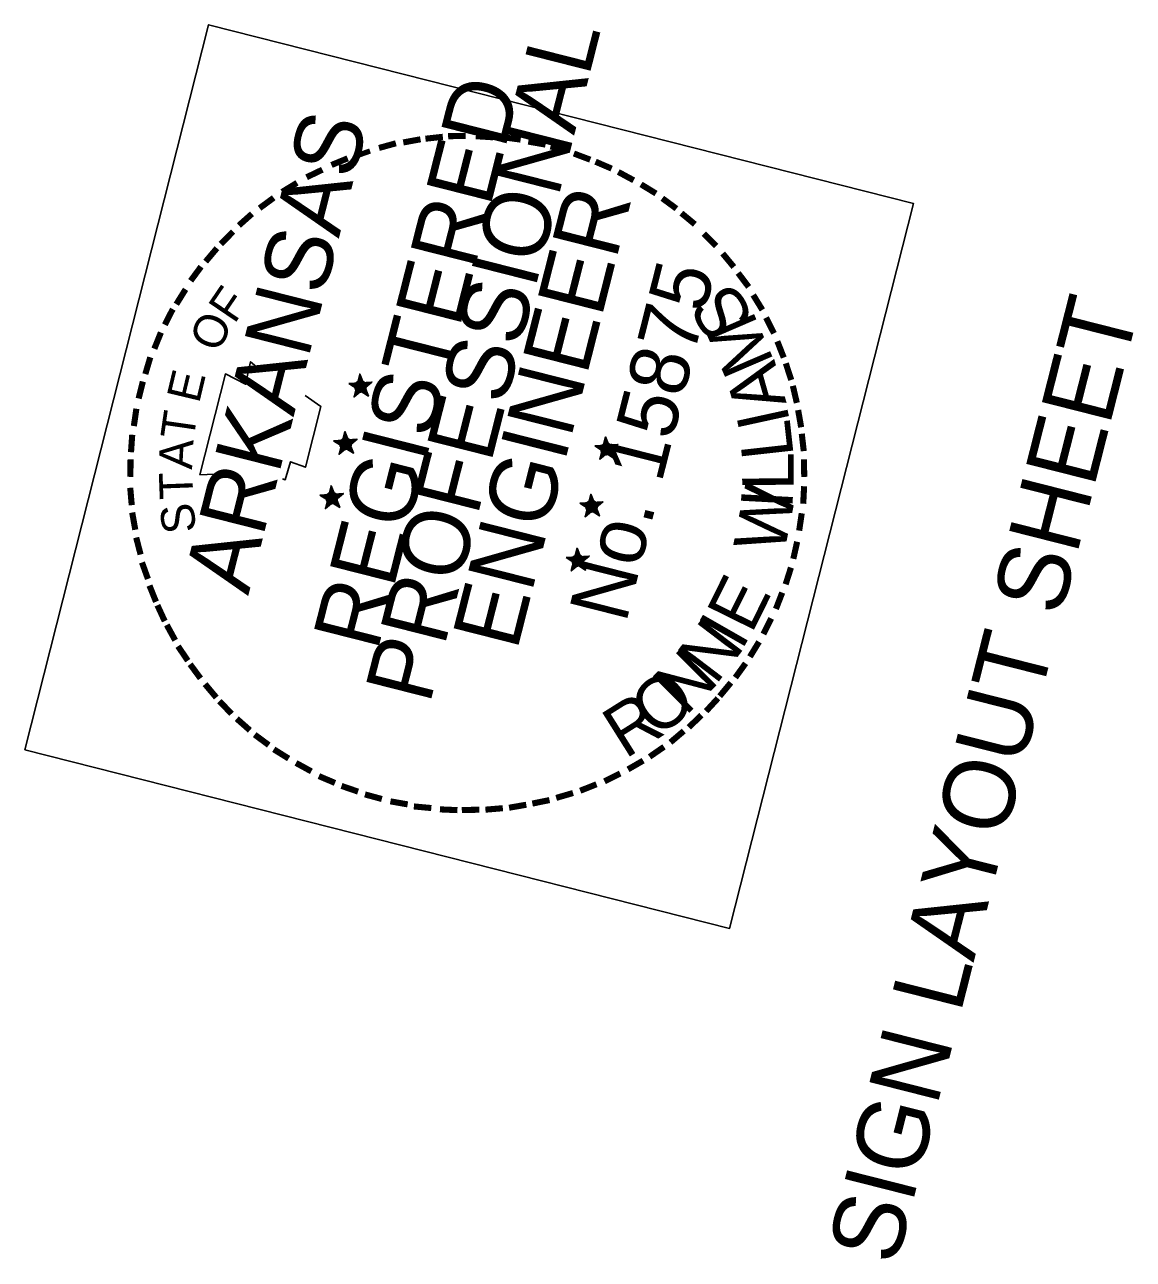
# Model space of a CAD drawing. Extents: x 670257 to 671518, y 737783 to 738188.
# Drawn here: x 670603.63 to 670611.9, y 738094.6 to 738103.81 of the extents above; entities that cross this region are included whole.
import ezdxf

# ---------------------------------------------------------------- set-up
doc = ezdxf.new("R2010")
doc.units = 0
for name, color, linetype in [('R_Border Notes', 7, 'Continuous'), ('R_Border PE', 7, 'Continuous'), ('R_Border Prem', 7, 'Continuous')]:
    doc.layers.add(name, color=color, linetype=linetype)

msp = doc.modelspace()

# ---------------------------------------------------------------- linework, layer by layer
at = {"layer": 'R_Border PE'}
for p, q in [((670606.1276, 738101.1982), (670606.1134, 738101.1219)), ((670606.1276, 738101.1982), (670606.1219, 738101.1249)), ((670606.1276, 738101.1982), (670606.1268, 738101.1237)), ((670606.1276, 738101.1982), (670606.1328, 738101.1067)), ((670606.1276, 738101.1982), (670606.1359, 738101.1394)), ((670606.1276, 738101.1982), (670606.1389, 738101.1412)), ((670606.1276, 738101.1982), (670606.1426, 738101.1454)), ((670606.0455, 738101.1288), (670606.1104, 738101.1304)), ((670606.1328, 738101.1067), (670606.0455, 738101.1288)), ((670606.0455, 738101.1288), (670606.1092, 738101.1255)), ((670606.0455, 738101.1288), (670606.1049, 738101.1189)), ((670606.0455, 738101.1288), (670606.1049, 738101.1086)), ((670606.0455, 738101.1288), (670606.1036, 738101.1037)), ((670606.0455, 738101.1288), (670606.1, 738101.0995)), ((670606.0846, 738101.0286), (670606.1328, 738101.1067)), ((670606.0846, 738101.0286), (670606.1078, 738101.0898)), ((670606.2184, 738101.1391), (670606.1328, 738101.1067)), ((670606.1919, 738101.0349), (670606.1328, 738101.1067)), ((670606.2184, 738101.1391), (670606.1401, 738101.1254)), ((670606.2184, 738101.1391), (670606.1413, 738101.1303)), ((670606.2184, 738101.1391), (670606.1492, 738101.1205)), ((670606.2184, 738101.1391), (670606.1521, 738101.1017)), ((670606.1919, 738101.0349), (670606.1521, 738101.1017)), ((670606.1919, 738101.0349), (670606.1521, 738101.0914)), ((670606.2184, 738101.1391), (670606.157, 738101.1108)), ((670606.2184, 738101.1391), (670606.1594, 738101.0999)), ((670606.1919, 738101.0349), (670606.16, 738101.1023)), ((670606.0846, 738101.0286), (670606.1121, 738101.0861)), ((670606.0846, 738101.0286), (670606.1145, 738101.0855)), ((670606.0846, 738101.0286), (670606.1236, 738101.0806)), ((670606.0846, 738101.0286), (670606.1284, 738101.0794)), ((670606.0846, 738101.0286), (670606.1333, 738101.0782)), ((670606.1919, 738101.0349), (670606.1315, 738101.0812)), ((670606.1919, 738101.0349), (670606.1393, 738101.0818)), ((670606.1919, 738101.0349), (670606.143, 738101.086)), ((670606.0164, 738100.7699), (670606.0022, 738100.6936)), ((670606.0164, 738100.7699), (670606.0107, 738100.6966)), ((670606.0164, 738100.7699), (670606.0155, 738100.6953)), ((670606.0164, 738100.7699), (670606.0216, 738100.6783)), ((670606.0164, 738100.7699), (670606.0247, 738100.7111)), ((670606.0164, 738100.7699), (670606.0283, 738100.7153)), ((670606.0164, 738100.7699), (670606.0314, 738100.7171)), ((670607.9614, 738100.7306), (670607.9478, 738100.6566)), ((670607.9614, 738100.7306), (670607.9563, 738100.6596)), ((670607.9614, 738100.7306), (670607.9612, 738100.6584)), ((670607.9614, 738100.7306), (670607.9672, 738100.6414)), ((670607.9614, 738100.7306), (670607.9697, 738100.6717)), ((670607.9614, 738100.7306), (670607.9758, 738100.6753)), ((670607.9614, 738100.7306), (670607.9788, 738100.6771)), ((670605.9319, 738100.7011), (670605.9992, 738100.7021)), ((670606.0216, 738100.6783), (670605.9319, 738100.7011)), ((670605.9319, 738100.7011), (670605.9955, 738100.6978)), ((670605.9319, 738100.7011), (670605.9937, 738100.6906)), ((670605.9319, 738100.7011), (670605.9912, 738100.6809)), ((670605.9319, 738100.7011), (670605.9924, 738100.6754)), ((670605.9319, 738100.7011), (670605.9894, 738100.6736)), ((670605.9734, 738100.6003), (670606.0216, 738100.6783)), ((670605.9734, 738100.6003), (670605.9942, 738100.6621)), ((670605.9734, 738100.6003), (670605.9991, 738100.6608)), ((670605.9734, 738100.6003), (670606.0033, 738100.6572)), ((670605.9734, 738100.6003), (670606.0124, 738100.6523)), ((670605.9734, 738100.6003), (670606.0172, 738100.6511)), ((670605.9734, 738100.6003), (670606.0221, 738100.6498)), ((670606.0813, 738100.609), (670606.0203, 738100.6529)), ((670606.1078, 738100.7132), (670606.0216, 738100.6783)), ((670606.0813, 738100.609), (670606.0216, 738100.6783)), ((670606.1078, 738100.7132), (670606.0277, 738100.7026)), ((670606.0813, 738100.609), (670606.0281, 738100.6535)), ((670606.1078, 738100.7132), (670606.0289, 738100.6971)), ((670606.0813, 738100.609), (670606.0318, 738100.6577)), ((670606.1078, 738100.7132), (670606.038, 738100.6922)), ((670606.1078, 738100.7132), (670606.0409, 738100.6734)), ((670606.0813, 738100.609), (670606.0409, 738100.6734)), ((670606.0813, 738100.609), (670606.0409, 738100.6631)), ((670606.1078, 738100.7132), (670606.0458, 738100.6825)), ((670606.1078, 738100.7132), (670606.0482, 738100.6716)), ((670606.0813, 738100.609), (670606.0488, 738100.674)), ((670607.9672, 738100.6414), (670607.8799, 738100.6635)), ((670607.8799, 738100.6635), (670607.9442, 738100.6627)), ((670607.8799, 738100.6635), (670607.9436, 738100.6603)), ((670607.8799, 738100.6635), (670607.9418, 738100.653)), ((670607.8799, 738100.6635), (670607.9393, 738100.6433)), ((670607.8799, 738100.6635), (670607.9381, 738100.6385)), ((670607.8799, 738100.6635), (670607.9368, 738100.6336)), ((670607.919, 738100.5633), (670607.9672, 738100.6414)), ((670608.0528, 738100.6739), (670607.9672, 738100.6414)), ((670608.0264, 738100.5697), (670607.9672, 738100.6414)), ((670608.0528, 738100.6739), (670607.9739, 738100.6577)), ((670608.0528, 738100.6739), (670607.9751, 738100.6626)), ((670608.0528, 738100.6739), (670607.9854, 738100.6523)), ((670608.0528, 738100.6739), (670607.9884, 738100.6334)), ((670608.0264, 738100.5697), (670607.9884, 738100.6334)), ((670608.0528, 738100.6739), (670607.9908, 738100.6431)), ((670608.0264, 738100.5697), (670607.9938, 738100.6346)), ((670608.0528, 738100.6739), (670607.9956, 738100.6316)), ((670607.919, 738100.5633), (670607.9416, 738100.6221)), ((670607.919, 738100.5633), (670607.9465, 738100.6209)), ((670607.919, 738100.5633), (670607.9507, 738100.6172)), ((670607.919, 738100.5633), (670607.958, 738100.6154)), ((670607.919, 738100.5633), (670607.9646, 738100.6111)), ((670607.919, 738100.5633), (670607.9695, 738100.6099)), ((670608.0264, 738100.5697), (670607.9653, 738100.6135)), ((670608.0264, 738100.5697), (670607.9756, 738100.6135)), ((670608.0264, 738100.5697), (670607.9798, 738100.6201)), ((670608.0264, 738100.5697), (670607.9865, 738100.6262)), ((670605.9138, 738100.3652), (670605.8996, 738100.2889)), ((670605.9138, 738100.3652), (670605.9081, 738100.2919)), ((670605.9138, 738100.3652), (670605.9129, 738100.2907)), ((670605.9138, 738100.3652), (670605.9189, 738100.2737)), ((670605.9138, 738100.3652), (670605.9221, 738100.3064)), ((670605.9138, 738100.3652), (670605.9257, 738100.3106)), ((670605.9138, 738100.3652), (670605.9287, 738100.3124)), ((670605.8293, 738100.2964), (670605.8966, 738100.2974)), ((670605.9189, 738100.2737), (670605.8293, 738100.2964)), ((670605.8293, 738100.2964), (670605.8929, 738100.2932)), ((670605.8293, 738100.2964), (670605.8917, 738100.2883)), ((670605.8293, 738100.2964), (670605.8892, 738100.2786)), ((670605.8293, 738100.2964), (670605.8898, 738100.2707)), ((670605.8293, 738100.2964), (670605.8868, 738100.2689)), ((670605.8707, 738100.1956), (670605.9189, 738100.2737)), ((670606.0051, 738100.3085), (670605.9189, 738100.2737)), ((670605.9787, 738100.2043), (670605.9189, 738100.2737)), ((670606.0051, 738100.3085), (670605.9251, 738100.2979)), ((670606.0051, 738100.3085), (670605.9263, 738100.2924)), ((670606.0051, 738100.3085), (670605.9353, 738100.2875)), ((670606.0051, 738100.3085), (670605.9383, 738100.2687)), ((670605.9787, 738100.2043), (670605.9383, 738100.2687)), ((670606.0051, 738100.3085), (670605.9432, 738100.2778)), ((670606.0051, 738100.3085), (670605.9456, 738100.2669)), ((670605.9787, 738100.2043), (670605.9462, 738100.2693)), ((670607.8502, 738100.3022), (670607.8366, 738100.2283)), ((670607.8502, 738100.3022), (670607.8451, 738100.2313)), ((670607.8502, 738100.3022), (670607.85, 738100.2301)), ((670607.8502, 738100.3022), (670607.856, 738100.2131)), ((670607.8502, 738100.3022), (670607.8585, 738100.2434)), ((670607.8502, 738100.3022), (670607.8622, 738100.2476)), ((670607.8502, 738100.3022), (670607.8682, 738100.2513)), ((670605.8707, 738100.1956), (670605.8916, 738100.2574)), ((670605.8707, 738100.1956), (670605.8964, 738100.2562)), ((670605.8707, 738100.1956), (670605.9007, 738100.2525)), ((670605.8707, 738100.1956), (670605.9103, 738100.25)), ((670605.8707, 738100.1956), (670605.9146, 738100.2464)), ((670605.8707, 738100.1956), (670605.9194, 738100.2452)), ((670605.9787, 738100.2043), (670605.9176, 738100.2482)), ((670605.9787, 738100.2043), (670605.9255, 738100.2488)), ((670605.9787, 738100.2043), (670605.9292, 738100.253)), ((670605.9787, 738100.2043), (670605.9383, 738100.2584)), ((670607.856, 738100.2131), (670607.7687, 738100.2352)), ((670607.7687, 738100.2352), (670607.833, 738100.2344)), ((670607.7687, 738100.2352), (670607.8324, 738100.232)), ((670607.7687, 738100.2352), (670607.8305, 738100.2247)), ((670607.7687, 738100.2352), (670607.8281, 738100.215)), ((670607.7687, 738100.2352), (670607.8269, 738100.2102)), ((670607.7687, 738100.2352), (670607.8232, 738100.2059)), ((670607.8078, 738100.135), (670607.856, 738100.2131)), ((670607.8078, 738100.135), (670607.8304, 738100.1938)), ((670607.8078, 738100.135), (670607.8353, 738100.1926)), ((670607.8078, 738100.135), (670607.8377, 738100.1919)), ((670607.8078, 738100.135), (670607.8468, 738100.1871)), ((670607.8078, 738100.135), (670607.8516, 738100.1858)), ((670607.8078, 738100.135), (670607.8565, 738100.1846)), ((670607.9151, 738100.1413), (670607.8547, 738100.1876)), ((670607.9416, 738100.2455), (670607.856, 738100.2131)), ((670607.9151, 738100.1413), (670607.856, 738100.2131)), ((670607.9416, 738100.2455), (670607.8627, 738100.2294)), ((670607.9416, 738100.2455), (670607.8645, 738100.2367)), ((670607.9151, 738100.1413), (670607.865, 738100.1876)), ((670607.9151, 738100.1413), (670607.8686, 738100.1918)), ((670607.9416, 738100.2455), (670607.8724, 738100.227)), ((670607.9151, 738100.1413), (670607.8753, 738100.1979)), ((670607.9151, 738100.1413), (670607.8754, 738100.2082)), ((670607.9416, 738100.2455), (670607.8778, 738100.2076)), ((670607.9416, 738100.2455), (670607.8796, 738100.2148)), ((670607.9416, 738100.2455), (670607.882, 738100.2039)), ((670607.9151, 738100.1413), (670607.8826, 738100.2063)), ((670607.7482, 738099.9), (670607.734, 738099.8236)), ((670607.7482, 738099.9), (670607.7425, 738099.8266)), ((670607.7482, 738099.9), (670607.7473, 738099.8254)), ((670607.7482, 738099.9), (670607.7533, 738099.8084)), ((670607.7482, 738099.9), (670607.7559, 738099.8387)), ((670607.7482, 738099.9), (670607.7595, 738099.8429)), ((670607.7482, 738099.9), (670607.7656, 738099.8466)), ((670607.6661, 738099.8305), (670607.731, 738099.8321)), ((670607.7533, 738099.8084), (670607.6661, 738099.8305)), ((670607.6661, 738099.8305), (670607.7298, 738099.8273)), ((670607.6661, 738099.8305), (670607.7279, 738099.82)), ((670607.6661, 738099.8305), (670607.7254, 738099.8103)), ((670607.6661, 738099.8305), (670607.7242, 738099.8055)), ((670607.6661, 738099.8305), (670607.7206, 738099.8012)), ((670607.7052, 738099.7304), (670607.7533, 738099.8084)), ((670607.8389, 738099.8409), (670607.7533, 738099.8084)), ((670607.8125, 738099.7367), (670607.7533, 738099.8084)), ((670607.8389, 738099.8409), (670607.7601, 738099.8248)), ((670607.8389, 738099.8409), (670607.7619, 738099.832)), ((670607.8389, 738099.8409), (670607.7698, 738099.8223)), ((670607.8125, 738099.7367), (670607.7727, 738099.8035)), ((670607.8389, 738099.8409), (670607.7751, 738099.8029)), ((670607.8389, 738099.8409), (670607.777, 738099.8101)), ((670607.8389, 738099.8409), (670607.7794, 738099.7992)), ((670607.8125, 738099.7367), (670607.78, 738099.8016)), ((670607.7052, 738099.7304), (670607.7284, 738099.7915)), ((670607.7052, 738099.7304), (670607.7326, 738099.7879)), ((670607.7052, 738099.7304), (670607.7351, 738099.7872)), ((670607.7052, 738099.7304), (670607.7441, 738099.7824)), ((670607.7052, 738099.7304), (670607.749, 738099.7811)), ((670607.7052, 738099.7304), (670607.7538, 738099.7799)), ((670607.8125, 738099.7367), (670607.752, 738099.7829)), ((670607.8125, 738099.7367), (670607.7623, 738099.7829)), ((670607.8125, 738099.7367), (670607.766, 738099.7871)), ((670607.8125, 738099.7367), (670607.7727, 738099.7932))]:
    msp.add_line(p, q, dxfattribs=at)
for points in [[(670605.3723, 738101.2402), (670605.313, 738101.2913), (670605.2754, 738101.1229), (670605.1247, 738101.1998), (670604.9336, 738100.4462)], [(670606.0455, 738101.1288), (670606.2184, 738101.1391), (670606.0846, 738101.0286), (670606.1276, 738101.1982), (670606.1919, 738101.0349), (670606.0455, 738101.1288)], [(670605.5501, 738100.4162), (670605.5719, 738100.4107), (670605.6112, 738100.5451), (670605.722, 738100.5041), (670605.837, 738100.9573), (670605.7208, 738101.0383)], [(670605.9319, 738100.7011), (670606.1078, 738100.7132), (670605.9734, 738100.6003), (670606.0164, 738100.7699), (670606.0813, 738100.609), (670605.9319, 738100.7011)], [(670607.8799, 738100.6635), (670608.0528, 738100.6739), (670607.919, 738100.5633), (670607.9614, 738100.7306), (670608.0264, 738100.5697), (670607.8799, 738100.6635)], [(670604.9336, 738100.4462), (670605.1507, 738100.4582)], [(670605.8293, 738100.2964), (670606.0051, 738100.3085), (670605.8707, 738100.1956), (670605.9138, 738100.3652), (670605.9787, 738100.2043), (670605.8293, 738100.2964)], [(670607.7687, 738100.2352), (670607.9416, 738100.2455), (670607.8078, 738100.135), (670607.8502, 738100.3022), (670607.9151, 738100.1413), (670607.7687, 738100.2352)], [(670607.6661, 738099.8305), (670607.8389, 738099.8409), (670607.7052, 738099.7304), (670607.7482, 738099.9), (670607.8125, 738099.7367), (670607.6661, 738099.8305)]]:
    msp.add_lwpolyline(points, dxfattribs=at)
for centre, radius in [((670606.1333, 738101.1063), 0.0431), ((670606.1333, 738101.1063), 0.039), ((670606.1333, 738101.1063), 0.0361), ((670606.1333, 738101.1063), 0.0332), ((670606.1333, 738101.1063), 0.0289), ((670606.1333, 738101.1063), 0.0269), ((670606.1333, 738101.1063), 0.0248), ((670606.1333, 738101.1063), 0.0213), ((670606.1333, 738101.1063), 0.0187), ((670606.1333, 738101.1063), 0.0155), ((670606.1333, 738101.1063), 0.0124), ((670606.1333, 738101.1063), 0.00924), ((670606.1333, 738101.1063), 0.00741), ((670606.1333, 738101.1063), 0.0036), ((670606.0219, 738100.6788), 0.0431), ((670606.0219, 738100.6788), 0.039), ((670606.0219, 738100.6788), 0.0361), ((670606.0219, 738100.6788), 0.0332), ((670606.0219, 738100.6788), 0.0289), ((670606.0219, 738100.6788), 0.0269), ((670606.0219, 738100.6788), 0.0248), ((670606.0219, 738100.6788), 0.0213), ((670606.0219, 738100.6788), 0.0187), ((670606.0219, 738100.6788), 0.0155), ((670606.0219, 738100.6788), 0.0124), ((670606.0219, 738100.6788), 0.00924), ((670606.0219, 738100.6788), 0.00741), ((670606.0219, 738100.6788), 0.0036), ((670607.9682, 738100.6399), 0.0431), ((670607.9682, 738100.6399), 0.039), ((670607.9682, 738100.6399), 0.0361), ((670607.9682, 738100.6399), 0.0332), ((670607.9682, 738100.6399), 0.0289), ((670607.9682, 738100.6399), 0.0269), ((670607.9682, 738100.6399), 0.0248), ((670607.9682, 738100.6399), 0.0213), ((670607.9682, 738100.6399), 0.0187), ((670607.9682, 738100.6399), 0.0155), ((670607.9682, 738100.6399), 0.0124), ((670607.9682, 738100.6399), 0.00924), ((670607.9682, 738100.6399), 0.00741), ((670607.9682, 738100.6399), 0.0036), ((670605.9193, 738100.2743), 0.0431), ((670605.9193, 738100.2743), 0.039), ((670605.9193, 738100.2743), 0.0361), ((670605.9193, 738100.2743), 0.0332), ((670605.9193, 738100.2743), 0.0289), ((670605.9193, 738100.2743), 0.0269), ((670605.9193, 738100.2743), 0.0248), ((670605.9193, 738100.2743), 0.0213), ((670605.9193, 738100.2743), 0.0187), ((670605.9193, 738100.2743), 0.0155), ((670605.9193, 738100.2743), 0.0124), ((670605.9193, 738100.2743), 0.00924), ((670605.9193, 738100.2743), 0.00741), ((670605.9193, 738100.2743), 0.0036), ((670607.8568, 738100.2124), 0.0431), ((670607.8568, 738100.2124), 0.039), ((670607.8568, 738100.2124), 0.0361), ((670607.8568, 738100.2124), 0.0332), ((670607.8568, 738100.2124), 0.0289), ((670607.8568, 738100.2124), 0.0269), ((670607.8568, 738100.2124), 0.0248), ((670607.8568, 738100.2124), 0.0213), ((670607.8568, 738100.2124), 0.0187), ((670607.8568, 738100.2124), 0.0155), ((670607.8568, 738100.2124), 0.0124), ((670607.8568, 738100.2124), 0.00924), ((670607.8568, 738100.2124), 0.00741), ((670607.8568, 738100.2124), 0.0036), ((670607.7542, 738099.8079), 0.0431), ((670607.7542, 738099.8079), 0.039), ((670607.7542, 738099.8079), 0.0361), ((670607.7542, 738099.8079), 0.0332), ((670607.7542, 738099.8079), 0.0289), ((670607.7542, 738099.8079), 0.0269), ((670607.7542, 738099.8079), 0.0248), ((670607.7542, 738099.8079), 0.0213), ((670607.7542, 738099.8079), 0.0187), ((670607.7542, 738099.8079), 0.0155), ((670607.7542, 738099.8079), 0.0124), ((670607.7542, 738099.8079), 0.00924), ((670607.7542, 738099.8079), 0.00741), ((670607.7542, 738099.8079), 0.0036)]:
    msp.add_circle(centre, radius, dxfattribs=at)
at = {"layer": 'R_Border Prem'}
msp.add_lwpolyline([(670603.6278, 738098.3965), (670604.9996, 738103.8053), (670610.258, 738102.4716), (670608.8862, 738097.0629)], close=True, dxfattribs=at)

# ---------------------------------------------------------------- texts
at = {"layer": 'R_Border Notes'}
msp.add_text('SIGN LAYOUT SHEET', height=0.533593, rotation=75.76855, dxfattribs=at).set_placement((670610.1307, 738094.5378))
at = {"layer": 'R_Border PE'}
for s, height, rotation, p in [('PROFESSIONAL', 0.499995, 75.76855, (670606.6485, 738098.7268)), ('REGISTERED', 0.5, 75.76855, (670606.2588, 738099.1223)), ('ARKANSAS', 0.5, 75.76855, (670605.2949, 738099.5421)), ('-', 0.4, 15.4369, (670606.2893, 738102.7305)), ('-', 0.3999, 10.43135, (670606.4568, 738102.7706)), ('-', 0.3999, 6.34138, (670606.6109, 738102.7985)), ('-', 0.4, 0.89181, (670606.7655, 738102.8186)), ('-', 0.4, 356.31789, (670606.9596, 738102.821)), ('-', 0.4, 352.36471, (670607.1542, 738102.8155)), ('-', 0.4, 350.09866, (670607.3348, 738102.7852)), ('-', 0.35, 19.44384, (670606.1218, 738102.6905)), ('-', 0.3999, 345.70922, (670607.4893, 738102.7537)), ('-', 0.3999, 339.28575, (670607.648, 738102.7083)), ('-', 0.3999, 22.42073, (670605.9535, 738102.6067)), ('-', 0.4, 336.76384, (670607.8036, 738102.6508)), ('-', 0.3999, 25.64828, (670605.7762, 738102.5176)), ('-', 0.3999, 331.53115, (670607.9617, 738102.5823)), ('-', 0.4, 31.34714, (670605.6079, 738102.4133)), ('ENGINEER', 0.5, 75.76855, (670607.2993, 738099.1266)), ('-', 0.4, 328.63664, (670608.1251, 738102.4945)), ('-', 0.4, 36.29826, (670605.4523, 738102.298)), ('-', 0.4, 323.65722, (670608.2739, 738102.4)), ('-', 0.3999, 41.63121, (670605.3106, 738102.1766)), ('-', 0.4, 320.38827, (670608.41, 738102.2958)), ('-', 0.3999, 45.40945, (670605.184, 738102.0437)), ('-', 0.4, 314.8398, (670608.5678, 738102.1552)), ('-', 0.4, 49.88964, (670605.0805, 738101.9203)), ('-', 0.4, 309.61379, (670608.7007, 738102.0183)), ('-', 0.4, 53.62364, (670604.9763, 738101.7842)), ('No. 15875', 0.44, 75.76855, (670608.1124, 738099.3326)), ('-', 0.4, 307.02232, (670608.8124, 738101.8791)), ('-', 0.4, 58.10475, (670604.8776, 738101.6184)), ('F', 0.2499, 55.83921, (670605.1921, 738101.567)), ('S', 0.3849, 121.46196, (670609.0814, 738101.6075)), ('-', 0.3999, 301.53388, (670608.9186, 738101.7284)), ('-', 0.4, 62.97344, (670604.8001, 738101.4756)), ('O', 0.2499, 66.22005, (670605.0779, 738101.351)), ('M', 0.3849, 113.32556, (670609.2223, 738101.2917)), ('-', 0.3999, 296.85364, (670609.0102, 738101.571)), ('-', 0.4, 67.93028, (670604.7292, 738101.3079)), ('-', 0.3999, 291.50488, (670609.0903, 738101.4088)), ('-', 0.4, 73.51159, (670604.6691, 738101.1323)), ('A', 0.3849, 105.76014, (670609.312, 738100.9828)), ('-', 0.4, 288.01764, (670609.1516, 738101.254)), ('E', 0.25, 76.60089, (670604.9281, 738100.9737)), ('-', 0.3999, 75.95478, (670604.6218, 738100.956)), ('-', 0.4, 283.12539, (670609.2026, 738101.0992)), ('-', 0.3999, 81.66537, (670604.5915, 738100.7651)), ('T', 0.25, 81.79131, (670604.8872, 738100.7004)), ('I', 0.3849, 102.33428, (670609.3391, 738100.8396)), ('-', 0.3999, 280.02017, (670609.2415, 738100.9269)), ('L', 0.3849, 96.33904, (670609.3656, 738100.5861)), ('-', 0.4, 85.9879, (670604.5733, 738100.5814)), ('-', 0.4, 276.48697, (670609.2688, 738100.7601)), ('A', 0.25, 86.98173, (670604.8761, 738100.484)), ('-', 0.3999, 89.3987, (670604.5703, 738100.4068)), ('L', 0.3849, 90.3438, (670609.3656, 738100.3312)), ('-', 0.3999, 271.24284, (670609.2858, 738100.5829)), ('T', 0.2499, 92.17215, (670604.8857, 738100.2675)), ('-', 0.3999, 94.94463, (670604.5823, 738100.2103)), ('W', 0.3849, 78.78155, (670609.2906, 738099.8459)), ('-', 0.4, 267.05431, (670609.2894, 738100.3938)), ('I', 0.3849, 86.91795, (670609.3536, 738100.1859)), ('-', 0.4, 100.07576, (670604.609, 738100.041)), ('S', 0.2499, 97.36257, (670604.9097, 738100.0267)), ('-', 0.3999, 261.58522, (670609.2754, 738100.2064)), ('-', 0.4, 104.56037, (670604.6479, 738099.8687)), ('-', 0.4, 257.36031, (670609.245, 738100.0052)), ('-', 0.4, 109.83212, (670604.7006, 738099.7006)), ('-', 0.4, 252.28682, (670609.2044, 738099.8247)), ('-', 0.3999, 112.00029, (670604.7595, 738099.5361)), ('E', 0.3849, 63.72208, (670609.0503, 738099.254)), ('-', 0.4, 248.88401, (670609.1437, 738099.6466)), ('-', 0.3999, 114.71921, (670604.8227, 738099.3988)), ('-', 0.3999, 118.7308, (670604.8974, 738099.2664)), ('N', 0.3849, 52.7308, (670608.7816, 738098.8721)), ('I', 0.3849, 60.29623, (670608.9745, 738099.1295)), ('-', 0.4, 243.32407, (670609.0698, 738099.4668)), ('-', 0.4, 124.1916, (670604.9861, 738099.1278)), ('-', 0.4, 238.56682, (670608.9867, 738099.3022)), ('N', 0.3849, 45.16538, (670608.5566, 738098.6424)), ('-', 0.3999, 126.38273, (670605.0778, 738099.0014)), ('-', 0.4, 234.32977, (670608.894, 738099.1503)), ('-', 0.4, 130.00102, (670605.1908, 738098.867)), ('O', 0.3849, 38.88465, (670608.3481, 738098.4755)), ('-', 0.3999, 230.36875, (670608.7923, 738099.0136)), ('R', 0.3849, 32.17569, (670608.1067, 738098.3236)), ('-', 0.3999, 227.33894, (670608.7022, 738098.9023)), ('-', 0.4, 133.83918, (670605.2989, 738098.7545)), ('-', 0.3999, 138.6399, (670605.4277, 738098.6418)), ('-', 0.4, 223.85834, (670608.5866, 738098.7821)), ('-', 0.3999, 143.54282, (670605.5595, 738098.5414)), ('-', 0.3999, 220.41489, (670608.4625, 738098.6691)), ('-', 0.3999, 148.16302, (670605.6987, 738098.4493)), ('-', 0.4, 214.70237, (670608.3287, 738098.5586)), ('-', 0.4, 209.99236, (670608.1853, 738098.4609)), ('-', 0.4, 151.22951, (670605.8615, 738098.359)), ('-', 0.3999, 206.48667, (670608.0225, 738098.368)), ('-', 0.3999, 156.96982, (670606.0249, 738098.2815)), ('-', 0.3999, 160.95489, (670606.1878, 738098.2221)), ('-', 0.4, 201.662, (670607.8585, 738098.291)), ('-', 0.4, 164.83079, (670606.3556, 738098.1718)), ('-', 0.4, 196.21567, (670607.6982, 738098.2285)), ('-', 0.3999, 169.96443, (670606.535, 738098.1366)), ('-', 0.3999, 174.71648, (670606.6992, 738098.113)), ('-', 0.4, 177.4835, (670606.8865, 738098.0991)), ('-', 0.4, 181.2264, (670607.0399, 738098.104)), ('-', 0.3999, 184.85597, (670607.2055, 738098.1162)), ('-', 0.3999, 189.83287, (670607.3669, 738098.1423)), ('-', 0.3999, 191.4974, (670607.5356, 738098.1769))]:
    msp.add_text(s, height=height, rotation=rotation, dxfattribs=at).set_placement(p)

doc.saveas('drawing.dxf')
